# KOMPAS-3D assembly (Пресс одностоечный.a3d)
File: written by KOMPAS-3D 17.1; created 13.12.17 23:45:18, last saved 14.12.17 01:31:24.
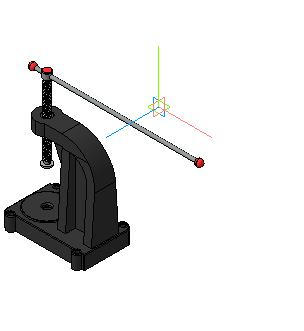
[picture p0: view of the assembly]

Referenced files in C:\Users\Yaroslav\Desktop\Дм Расчтека 1\Детали Компас 3D\: Крышка.m3d, Корпус.m3d, Гайка.m3d, Ручка.m3d, Рукоятка.m3d, Сплошная пята.m3d, Винт.m3d
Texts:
  Ручка Ручка (1)
  Сплошная пята Сплошная пята
  Ручка Ручка (2)
  Точка начала. Х
  Точка начала. Y
  Точка начала. Z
